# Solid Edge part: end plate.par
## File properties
Author: Binay
Template: sync ansi part.par
Last saved by: Cadcim
Revision: 6
Application: Solid Edge
Accuracy: 0.990
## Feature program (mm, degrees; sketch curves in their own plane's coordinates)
sketch for "unnamed Hole 1" plane through (74.0576, 73.9259, 6.35) normal (0, 0, 1) x-axis (1, 0, 0)
  hole centre (-38.8262, -36.609) bore radius 3.302
hole "unnamed Hole 1" through
pattern "unnamed Pattern 1" of "unnamed Hole 1"
pattern "unnamed Pattern 2" of "unnamed Hole 1"
pattern "PatternOccurrence_1"  XCount = 2; YCount = 2; XOffset = 76.2 mm; YOffset = 76.2 mm
hole "unnamed Hole 2" through
hole "unnamed Hole 3" through
hole "unnamed Hole 4" through
sketch for "Hole_5" plane through (73.6248, 74.4917, 6.35) normal (0, 0, 1) x-axis (1, 0, 0)
  hole centre (-0.2934, 0.9253) bore radius 12.7
hole "Hole_5" diameter 25.4 through
pattern "unnamed Pattern 3" of "Hole_5"
sketch for "Hole_6" plane through (74.8044, 76.257, 6.35) normal (0, 0, 1) x-axis (1, 0, 0)
  hole centre (-1.4729, 19.7975) bore radius 2.413
hole "Hole_6" diameter 4.826 through
sketch for "unnamed Hole 5" plane through (95.4419, 55.6195, 6.35) normal (0, 0, 1) x-axis (1, 0, 0)
  hole centre (-1.4729, 19.7975) bore radius 2.413
hole "unnamed Hole 5" through
sketch for "unnamed Hole 6" plane through (74.8044, 74.577, 6.35) normal (0, 0, 1) x-axis (1, 0, 0)
  hole centre (-1.4729, 19.7975) bore radius 2.413
hole "unnamed Hole 6" through
pattern "unnamed Pattern 4" of "Hole_6", "unnamed Hole 6"
sketch for "unnamed Hole 7" plane through (51.2211, 55.6195, 6.35) normal (0, 0, 1) x-axis (-1, 0, 0)
  hole centre (-1.4729, 19.7975) bore radius 2.413
hole "unnamed Hole 7" through
pattern "unnamed Pattern 5" of "unnamed Hole 5", "unnamed Hole 7"
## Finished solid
Body 1: solid body, 15 faces, 30 edges, 8 vertices.
  Faces by surface: cylinder 9, plane 6
  Edges by curve: circle 18, line 12
Bounding box of the edges (mm): 101.600 x 101.600 x 12.700, from (22.5315, 24.617, -6.35) to (124.1315, 126.217, 6.35).
Cylindrical faces by radius (mm): R2.413 x4, R3.302 x4, R12.7 x1
Planar faces by outward normal: +x 1, +y 1, +z 1, -x 1, -y 1, -z 1
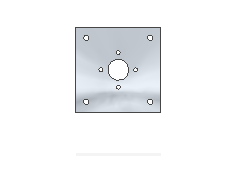
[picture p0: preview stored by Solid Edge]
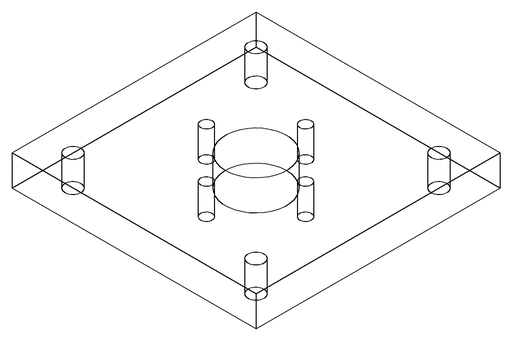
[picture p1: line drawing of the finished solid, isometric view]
